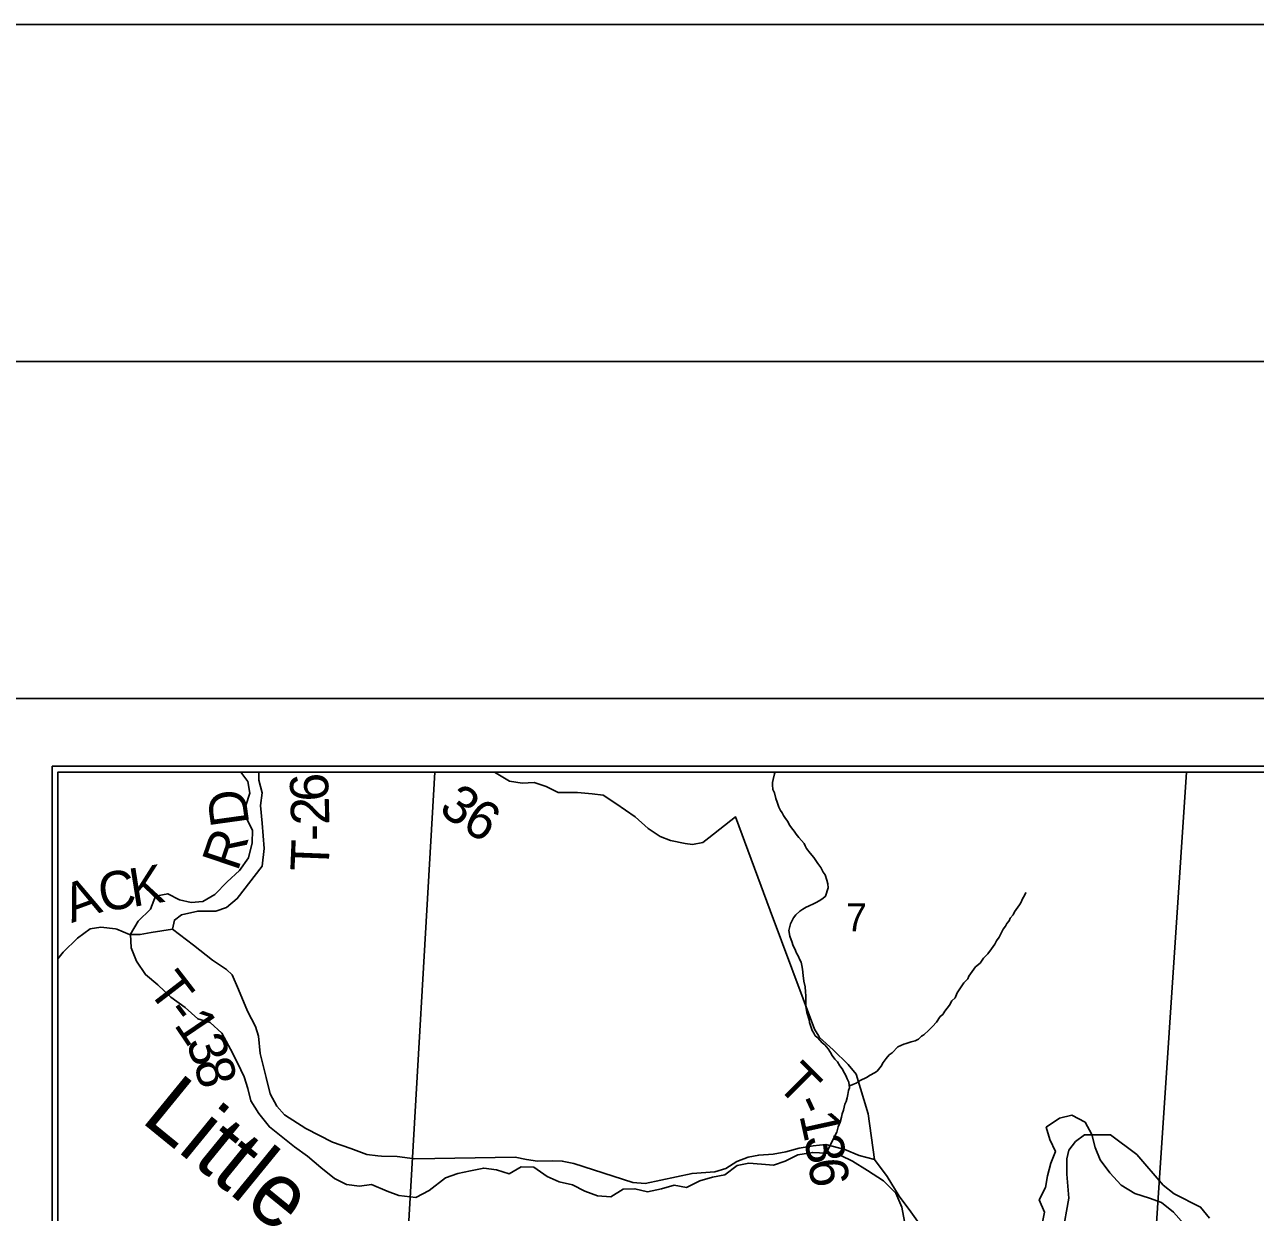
# Model space of a CAD drawing. Extents: x 0 to 34, y 0 to 22.
# Drawn here: x 2.059 to 3.885, y 20.238 to 22 of the extents above; entities that cross this region are included whole.
import ezdxf

# ---------------------------------------------------------------- set-up
doc = ezdxf.new("R2010")
doc.units = 0
for name, color, linetype in [('GM_X_County', 7, 'Continuous'), ('GM_X_County_Road', 7, 'Continuous'), ('GM_X_Minor_River', 7, 'Continuous'), ('GM_X_Minor_River_Text', 7, 'Continuous'), ('GM_X_Section', 7, 'Continuous'), ('GM_X_Section_Text', 7, 'Continuous'), ('GM_X_Township', 7, 'Continuous'), ('GM_X_Township_Road', 7, 'Continuous'), ('GM_X_Township_Road_Text', 7, 'Continuous'), ('GM_X_Township_ROW', 7, 'Continuous'), ('SH_Border', 7, 'Continuous'), ('SH_Cut_Line', 7, 'Continuous'), ('SH_Data', 7, 'Continuous')]:
    doc.layers.add(name, color=color, linetype=linetype)

msp = doc.modelspace()

# ---------------------------------------------------------------- linework, layer by layer
at = {"layer": 'GM_X_County'}
msp.add_lwpolyline([(8.9084, 15.63), (8.9084, 20.8908), (2.1084, 20.8908), (2.1084, 19.9847)], dxfattribs=at)
at = {"layer": 'GM_X_County_Road'}
msp.add_lwpolyline([(3.5983, 20.2065), (3.6081, 20.2586), (3.6048, 20.2943), (3.6048, 20.3171), (3.6081, 20.3301), (3.6178, 20.3431), (3.6309, 20.3529), (3.6699, 20.3529), (3.7089, 20.3236), (3.748, 20.2781), (3.7642, 20.2651), (3.8033, 20.2455), (3.8163, 20.2293)], dxfattribs=at)
at = {"layer": 'GM_X_Minor_River'}
for points in [[(2.3802, 20.8908), (2.3905, 20.877), (2.3935, 20.8595), (2.3874, 20.8413), (2.3873, 20.8239), (2.3971, 20.8049), (2.397, 20.7859), (2.3916, 20.7639), (2.3779, 20.745), (2.3596, 20.7283), (2.3414, 20.7094), (2.3239, 20.6989), (2.3065, 20.6974), (2.2891, 20.7013), (2.2717, 20.7104), (2.2535, 20.7067), (2.2459, 20.6878), (2.2276, 20.6696), (2.2162, 20.6507), (2.2176, 20.6302), (2.2251, 20.6104), (2.2386, 20.5906), (2.2567, 20.5754), (2.2764, 20.5571), (2.2975, 20.5418), (2.3164, 20.5251), (2.3345, 20.5197), (2.3519, 20.5037), (2.3646, 20.4801), (2.3752, 20.4596), (2.3849, 20.439), (2.3902, 20.4216), (2.3946, 20.4033), (2.4067, 20.3843), (2.4225, 20.3645), (2.4398, 20.3508), (2.4595, 20.3348), (2.4791, 20.321), (2.4987, 20.3043), (2.5191, 20.2882), (2.5365, 20.2791), (2.5562, 20.2767), (2.5736, 20.2789), (2.597, 20.269), (2.6144, 20.2628), (2.6394, 20.2597), (2.6591, 20.2703), (2.6834, 20.2891), (2.7016, 20.2952), (2.7206, 20.2996), (2.7403, 20.3034), (2.7592, 20.301), (2.7781, 20.2949), (2.7956, 20.3054), (2.8145, 20.3046), (2.8342, 20.2909), (2.8523, 20.2832), (2.872, 20.2786)], [(3.2478, 20.3258), (3.2638, 20.3569), (3.2658, 20.3645), (3.2686, 20.3716), (3.2706, 20.3788), (3.2718, 20.3841), (3.2735, 20.3894), (3.2755, 20.3985), (3.2775, 20.4022), (3.2791, 20.4079), (3.2803, 20.4128), (3.2812, 20.4185), (3.2824, 20.4223), (3.2821, 20.4265), (3.2814, 20.431), (3.2792, 20.436), (3.2774, 20.441), (3.2752, 20.4444), (3.2719, 20.4509), (3.2685, 20.4552), (3.2649, 20.4609), (3.2608, 20.4652), (3.2571, 20.4706), (3.2545, 20.4748), (3.2508, 20.4805), (3.246, 20.4863), (3.2423, 20.4894), (3.2356, 20.4967), (3.2318, 20.4998), (3.2296, 20.5037), (3.2274, 20.5075), (3.2235, 20.5197), (3.2228, 20.5235), (3.2192, 20.5342), (3.2178, 20.5434), (3.218, 20.5517), (3.2177, 20.5555), (3.2177, 20.5589), (3.2175, 20.565), (3.2168, 20.5722), (3.2151, 20.5806), (3.2141, 20.589), (3.2127, 20.5985), (3.2117, 20.6042), (3.211, 20.6088), (3.2092, 20.6126), (3.2067, 20.6184), (3.2041, 20.6222), (3.2026, 20.6264), (3.1986, 20.6348), (3.1975, 20.6383), (3.1939, 20.6478), (3.1925, 20.6558), (3.195, 20.666), (3.1997, 20.675), (3.2028, 20.6792), (3.209, 20.6848), (3.2132, 20.6877), (3.2185, 20.6907), (3.222, 20.6921), (3.23, 20.6962), (3.2334, 20.6973), (3.2376, 20.6998), (3.243, 20.7032), (3.2469, 20.7069), (3.2512, 20.7194), (3.2506, 20.7254), (3.2492, 20.7304), (3.2463, 20.7384), (3.2437, 20.7423), (3.2419, 20.7457), (3.24, 20.7495), (3.2356, 20.7553), (3.2297, 20.7645), (3.2241, 20.7707), (3.2189, 20.7776), (3.2167, 20.7815), (3.2153, 20.7849), (3.2075, 20.7941), (3.2034, 20.7988), (3.2005, 20.8034), (3.1967, 20.8084), (3.1942, 20.8118), (3.1905, 20.818), (3.1868, 20.8234), (3.185, 20.8268), (3.1827, 20.8306), (3.1802, 20.8341), (3.1776, 20.8391), (3.1755, 20.8463), (3.1733, 20.8517), (3.1712, 20.8604), (3.169, 20.865), (3.1683, 20.8723), (3.1684, 20.8757), (3.1692, 20.8798), (3.1716, 20.8885), (3.1725, 20.8908)], [(3.2817, 20.4249), (3.2874, 20.4275), (3.2927, 20.4293), (3.2985, 20.4334), (3.3076, 20.4378), (3.3134, 20.4411), (3.3199, 20.4448), (3.3237, 20.4474), (3.3295, 20.4545), (3.3326, 20.4602), (3.3369, 20.4662), (3.3416, 20.4714), (3.3458, 20.4747), (3.3543, 20.4833), (3.3588, 20.4851), (3.3631, 20.4874), (3.3665, 20.4884), (3.3741, 20.4906), (3.3798, 20.4924), (3.3848, 20.4946), (3.3894, 20.4991), (3.3928, 20.5013), (3.4002, 20.508), (3.4056, 20.5136), (3.4114, 20.5199), (3.4172, 20.5282), (3.421, 20.5312), (3.4238, 20.5361), (3.4311, 20.5454), (3.4346, 20.5514), (3.4393, 20.5563), (3.4424, 20.5635), (3.4521, 20.5781), (3.4583, 20.5845), (3.4595, 20.5882), (3.4669, 20.5984), (3.4696, 20.6021), (3.4765, 20.6077), (3.4812, 20.6148), (3.4877, 20.6212), (3.4932, 20.6287), (3.4982, 20.6358), (3.5006, 20.6407), (3.5045, 20.6463), (3.5068, 20.6508), (3.5107, 20.658), (3.5142, 20.6625), (3.5158, 20.6663), (3.5193, 20.6704), (3.5209, 20.6745), (3.5251, 20.6794), (3.5275, 20.6839), (3.5345, 20.694), (3.5372, 20.6982), (3.5388, 20.7019), (3.5407, 20.7053), (3.5439, 20.7117), (3.5444, 20.7124)], [(3.5685, 20.2206), (3.5716, 20.2381), (3.5641, 20.2563), (3.5733, 20.2745), (3.5764, 20.2919), (3.581, 20.3109), (3.5879, 20.3283), (3.5796, 20.3458), (3.5744, 20.3641), (3.5942, 20.3776), (3.6124, 20.3821), (3.632, 20.3714), (3.6418, 20.3532), (3.647, 20.3342), (3.6545, 20.3159), (3.6688, 20.2962), (3.6854, 20.2779), (3.7058, 20.2657), (3.7277, 20.2587), (3.7451, 20.2526), (3.7632, 20.2381), (3.7783, 20.2206)], [(2.872, 20.2786), (2.8901, 20.2694), (2.909, 20.2625), (2.9287, 20.2609), (2.9469, 20.2722), (2.9644, 20.2729), (2.9833, 20.2683), (3.0037, 20.2728), (3.0227, 20.278), (3.0409, 20.2749), (3.0606, 20.2847), (3.0795, 20.29), (3.0977, 20.2937), (3.116, 20.3073), (3.1334, 20.311), (3.1523, 20.3094), (3.1697, 20.3079), (3.1872, 20.3139), (3.2062, 20.3229), (3.2281, 20.3266), (3.2478, 20.3258), (3.2698, 20.3219), (3.2872, 20.3135), (3.3091, 20.2998), (3.3332, 20.2845), (3.3513, 20.2662), (3.3603, 20.2457), (3.364, 20.2244)]]:
    msp.add_lwpolyline(points, dxfattribs=at)
at = {"layer": 'GM_X_Section'}
for p, q in [((3.7825, 20.8908), (2.6675, 20.8908)), ((4.8624, 20.8908), (3.7825, 20.8908))]:
    msp.add_line(p, q, dxfattribs=at)
for points in [[(2.6675, 20.8908), (2.6266, 20.1828), (3.731, 20.118), (3.7825, 20.8908)], [(3.7825, 20.8908), (3.731, 20.118), (4.8149, 20.0525), (4.8624, 20.8908)]]:
    msp.add_lwpolyline(points, dxfattribs=at)
at = {"layer": 'GM_X_Township'}
msp.add_lwpolyline([(5.9855, 20.8908), (2.1084, 20.8908), (2.1084, 19.9847)], dxfattribs=at)
at = {"layer": 'GM_X_Township_Road'}
for points in [[(2.2788, 20.6581), (2.2815, 20.6714), (2.2921, 20.6794), (2.3161, 20.6847), (2.3427, 20.6847), (2.3586, 20.69), (2.3746, 20.7033), (2.4118, 20.7512), (2.4145, 20.7778), (2.4118, 20.815), (2.4092, 20.8416), (2.4118, 20.8602), (2.4065, 20.8789), (2.4065, 20.8908)], [(2.7564, 20.8908), (2.7784, 20.8774), (2.797, 20.8748), (2.8151, 20.8755), (2.8326, 20.8694), (2.8507, 20.8607), (2.8791, 20.8607), (2.9011, 20.8588), (2.9174, 20.8569), (2.936, 20.8443), (2.9647, 20.8246), (2.9841, 20.8071), (3.0019, 20.7953), (3.0174, 20.7896), (3.039, 20.7851), (3.05, 20.7836), (3.0651, 20.7866), (3.0742, 20.7934), (3.1136, 20.8245), (3.1652, 20.6854)], [(2.1084, 20.6141), (2.1165, 20.6236), (2.1378, 20.6448), (2.1564, 20.6582), (2.1724, 20.6608), (2.1944, 20.6584), (2.1963, 20.6581), (2.215, 20.6502), (2.2309, 20.6502), (2.2469, 20.6528), (2.2788, 20.6581)], [(2.2788, 20.6581), (2.3097, 20.6342), (2.3382, 20.612), (2.3587, 20.5979), (2.367, 20.5903), (2.3768, 20.5683), (2.3897, 20.5364), (2.4018, 20.5137), (2.406, 20.4992), (2.4086, 20.4734), (2.4177, 20.4381), (2.4234, 20.4138), (2.4332, 20.3952), (2.4446, 20.3823), (2.4764, 20.3622), (2.5158, 20.3421), (2.5431, 20.3326), (2.5669, 20.3238), (2.583, 20.3218)], [(3.237, 20.4992), (3.2382, 20.4973), (3.2582, 20.4791), (3.2806, 20.4574), (3.2923, 20.443), (3.3105, 20.3842), (3.3199, 20.3162)], [(2.583, 20.3218), (2.5885, 20.3212), (2.612, 20.3208), (2.6378, 20.3173), (2.7866, 20.3199), (2.8037, 20.3161), (2.82, 20.3138), (2.8419, 20.3142), (2.8567, 20.3138), (2.8737, 20.3104), (2.9612, 20.2819), (2.9798, 20.2807), (3.0491, 20.2955), (3.0828, 20.2981), (3.0991, 20.3031), (3.1154, 20.3133), (3.1324, 20.3197), (3.148, 20.3228), (3.1696, 20.3243), (3.1881, 20.3277), (3.2082, 20.333), (3.2287, 20.3364), (3.2476, 20.3387), (3.2756, 20.3311), (3.2972, 20.3219), (3.3199, 20.3162), (3.3385, 20.2908), (3.3563, 20.2616), (3.3737, 20.2388), (3.3908, 20.2141)]]:
    msp.add_lwpolyline(points, dxfattribs=at)
at = {"layer": 'GM_X_Township_ROW'}
msp.add_lwpolyline([(3.1652, 20.6854), (3.2306, 20.5095), (3.237, 20.4992)], dxfattribs=at)
at = {"layer": 'SH_Border'}
msp.add_lwpolyline([(1.5, 21.5), (33.5, 21.5), (33.5, 0.5), (1.5, 0.5)], close=True, dxfattribs=at)
at = {"layer": 'SH_Cut_Line'}
msp.add_lwpolyline([(0, 0), (34, 0), (34, 22), (0, 22)], close=True, dxfattribs=at)
at = {"layer": 'SH_Data'}
for p, q in [((2, 21), (9, 21)), ((2.1, 20.9), (2.1, 14.1)), ((2.1, 20.9), (8.9, 20.9))]:
    msp.add_line(p, q, dxfattribs=at)

# ---------------------------------------------------------------- texts
at = {"layer": 'GM_X_Minor_River_Text'}
msp.add_text('Little', height=0.09468, rotation=320.7841, dxfattribs=at).set_placement((2.2299, 20.3736))
at = {"layer": 'GM_X_Section_Text'}
msp.add_text('7', height=0.0419, rotation=0, dxfattribs=at).set_placement((3.2773, 20.6545))
at = {"layer": 'GM_X_Township_Road_Text'}
for s, rotation, p in [('6', 91.8867, (2.5105, 20.8483)), ('D', 97.9096, (2.3927, 20.8144)), ('3', 321.2677, (2.6715, 20.8335)), ('2', 91.5319, (2.5115, 20.8129)), ('6', 328.8432, (2.7055, 20.8069)), ('-', 90.9404, (2.5119, 20.789)), ('R', 71.2574, (2.3751, 20.7422)), ('T', 87.6723, (2.5101, 20.743)), ('K', 9.0895, (2.2195, 20.6908)), ('C', 9.3273, (2.1735, 20.6832)), ('A', 19.9975, (2.1292, 20.6669)), ('T', 307.6203, (2.2405, 20.5678)), ('1', 304.0213, (2.2799, 20.5162)), ('-', 306.948, (2.2663, 20.5342)), ('3', 290.6231, (2.2979, 20.4903)), ('8', 285.4606, (2.3098, 20.4588)), ('T', 315.014, (3.1722, 20.4258)), ('-', 294.8708, (3.1992, 20.4001)), ('1', 282.4413, (3.208, 20.382)), ('3', 279.1194, (3.2154, 20.3487)), ('6', 278.5768, (3.2209, 20.3142))]:
    msp.add_text(s, height=0.0568, rotation=rotation, dxfattribs=at).set_placement(p)

doc.saveas('drawing.dxf')
